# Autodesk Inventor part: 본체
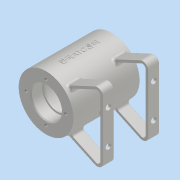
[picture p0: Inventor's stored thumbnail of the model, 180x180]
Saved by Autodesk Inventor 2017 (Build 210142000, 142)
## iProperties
Part Number: 본체
Material: 알루미늄 6061
Document SubType Name: Modeling
Designer: Administrator
Density: 2.7 g/cm^3
Appearance: 알루미늄 - 평지
Mass: 310.254 g
Surface Area: 354.969 cm^2
Volume: 114.909 cm^3
Author: Administrator
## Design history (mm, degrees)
sketch "스케치1"
  geometry: C1 r 29 at (0, 0); 1 further point
  constraints: 1 centre point, 1 coincident
  dimensions: "d0" = 58 diameter of C1
extrude "돌출1" new body sketch "스케치1" distance "d1" = 35; taper "d3" = 0 deg; dims "d2" = 35, "d4" = 0
sketch "스케치2"
  geometry: C1 r 21 at (0, 0); 1 further point
  constraints: 1 centre point, 1 coincident
  dimensions: "d5" = 42 diameter of C1
extrude "돌출2" cut sketch "스케치2" distance "d6" = 21; taper "d8" = 0 deg; dims "d7" = 21, "d9" = 0
sketch "스케치3"
  geometry: C1 r 14 at (0, 0); 1 further point
  constraints: 1 centre point, 1 coincident
  dimensions: "d10" = 28 diameter of C1
extrude "돌출3" cut sketch "스케치3" distance "d11" = 23; taper "d13" = 0 deg; dims "d12" = 23, "d14" = 0
sketch "스케치4"
  geometry: C1 r 14 at (0, 0) reference; C2 r 16 at (0, 0); 1 further point
  constraints: 1 centre point, 1 coincident
  dimensions: "d15" = 32 diameter of C2
extrude "돌출4" cut sketch "스케치4" distance "d16" = 12; taper "d17" = 0 deg
sketch "스케치5"
  geometry: C1 r 16 at (0, 0); 1 further point
  constraints: 1 centre point, 1 coincident
  dimensions: "d18" = 32 diameter of C1
extrude "돌출5" cut sketch "스케치5" distance "d19" = 12; taper "d20" = 0 deg
sketch "스케치6"
  geometry: 2 further points
  constraints: 1 horizontal alignment
  dimensions: "d21" = 21 distance of point (0, 0) point (-21, 0)
hole "구멍1" sketch "스케치6" at (-21, 0) diameter "d22" = 3.242; stored, may be unused: countersink angle "d26" = 90 deg, drill point angle "d28" = 118 deg; dims "d23" = 8, "d24" = 4, "d25" = 2, "d27" = 10
sketch "스케치7"
  geometry: 2 further points
  constraints: 1 horizontal alignment
  dimensions: "d32" = 21 distance of point (0, 0) point (-21, 0)
hole "구멍2" sketch "스케치7" at (-21, 0) diameter "d33" = 3.242; stored, may be unused: countersink angle "d37" = 90 deg, drill point angle "d39" = 118 deg; dims "d34" = 8, "d35" = 4, "d36" = 2, "d38" = 10
sketch "스케치8"
  geometry: L1 (0, 0)-(-30.07, -10.945); L2 (0, 0)-(32, 0); L3 (-30.07, -10.945)-(-28.018, -16.583); L4 (-23.397, -8.516)-(-21.345, -14.154); L5 (-21.345, -14.154)-(-28.018, -16.583)
  constraints: 10 end point, 2 perpendicular, 1 equal length, 1 horizontal, 1 parallel, 1 point on line
  dimensions: "d43" = 160 deg angle of L1 L2; "d45" = 32 distance of L1.start L1.end; "d46" = 6 distance of L1.end L3.end; "d47" = 6.67327 horizontal distance of L4.end L3.end
revolve "회전1" sketch "스케치8" stored, may be unused: angle "d48" = 90 deg
sketch "스케치9"
  geometry: 2 further points
  constraints: 2 coincident
hole "구멍3" sketch "스케치9" at (0, 0) diameter "d49" = 5.188; stored, may be unused: countersink angle "d53" = 90 deg, drill point angle "d55" = 118 deg; dims "d50" = 20, "d51" = 4, "d52" = 2, "d54" = 29
node "작업 평면1"
sketch "스케치12"
  geometry: C1 r 5 at (0, 0); 1 further point
  constraints: 1 centre point, 1 coincident
  dimensions: "d59" = 10 diameter of C1
extrude "돌출6" join sketch "스케치12" stored distance "d60" = 10; taper "d61" = 0 deg
node "작업 평면2"
sketch "스케치13"
  geometry: L1 (-55, 30.582)-(-55, -30.582); L2 (0, 0)-(0, -50.41); L3 (-46.464, -36.02)-(-17.993, -22.743); L4 (-55, -40)-(-23.585, -40); L5 (-46.464, 36.02)-(-17.993, 22.743); L6 (-55, 40)-(-23.585, 40); L7 (-20.438, 20.574)-(-47.732, 33.301); L8 (-52, 30.582)-(-52, -30.582); L9 (-47.732, -33.301)-(-20.438, -20.574); A1 r 29 centre (0, 0) between (-17.993, 22.743) and (-17.993, -22.743) reference; A2 r 6 centre (-49, -30.582) between (-55, -30.582) and (-46.464, -36.02); A3 r 6 centre (-49, 30.582) between (-46.464, 36.02) and (-55, 30.582); A4 r 3 centre (-49, 30.582) between (-47.732, 33.301) and (-52, 30.582); A5 r 3 centre (-49, -30.582) between (-52, -30.582) and (-47.732, -33.301); 2 further points
  constraints: 18 end point, 12 point on circle, 4 centre point, 4 point on line, 4 tangent, 2 equal length, 2 horizontal, 1 equal radius, 1 horizontal alignment, 1 midpoint, 1 parallel, 1 vertical, 2 other
  dimensions: "d63" = 55 distance from line of L1 point (0, 0); "d64" = 80 distance of L6.start L4.start; "d65" = 25 deg angle of L4 L3; "d66" = 25 deg angle of L5 L6; "d67" = 50.40972 distance of L2.start L2.end; "d71" = 6 radius of A2; "d72" = 3 distance between parallel lines of L5 L7; "d73" = 3 distance between parallel lines of L1 L8; "d74" = 3 distance between parallel lines of L3 L9
extrude "돌출7" join sketch "스케치13" distance "d75" = 12; taper "d76" = 0 deg
sketch "스케치14"
  geometry: L1 (0, 0)-(61.164, 0) reference; L2 (61.164, 0)-(61.164, 12) reference; L3 (0, 12)-(61.164, 12) reference; L4 (0, 0)-(0, 12) reference; C1 r 3 at (48.582, 6); C2 r 3 at (12.582, 6); 1 further point
  constraints: 2 centre point
  dimensions: "d77" = 6 diameter of C1; "d78" = 6 diameter of C2; "d80" = 6 distance from line of L3 C1.centre; "d81" = 6 distance from line of L3 C2.centre; "d82" = 36 distance of C2.centre C1.centre; "d83" = 18 horizontal distance of point (30.582, -18) C1.centre
extrude "돌출8" cut sketch "스케치14" distance "d84" = 12; taper "d85" = 0 deg
sketch "스케치15"
  geometry: 2 further points
  constraints: 1 coincident
hole "구멍4" sketch "스케치15" at (0, 0) diameter "d86" = 5.188; stored, may be unused: countersink angle "d90" = 90 deg, drill point angle "d92" = 118 deg; dims "d87" = 6, "d88" = 4, "d89" = 2, "d91" = 8
sketch "스케치16"
  geometry: C1 r 1.5 at (0, 0); 1 further point
  constraints: 1 centre point, 1 coincident
  dimensions: "d93" = 3 diameter of C1
extrude "돌출9" cut sketch "스케치16" distance "d94" = 34.75; taper "d95" = 0 deg
fillet "모깎기1" dims "d96" = 1
fillet "모깎기2" dims "d97" = 0.5
fillet "모깎기3" dims "d98" = 0.5
fillet "모깎기4" dims "d99" = 0.3
fillet "모깎기5" dims "d100" = 3
fillet "모깎기6" dims "d101" = 3
chamfer "모따기1" distance "d102" = 1; stored, may be unused: second distance "d103" = 2, angle "d104" = 45 deg
node "작업 평면4"
sketch "스케치18"
  geometry: L1 (-29, -35)-(29, -35) reference; L2 (-29, -35)-(-29, 35) reference; 2 further points
  constraints: 1 other
  dimensions: "d111" = 35 distance from line of L1 point (0, 0); "d112" = 29 distance from line of L2 point (0, 0)
feature "엠보싱2" sketch "스케치18" dims "d113" = 0.5, "d114" = 0
node "솔리드1"
pattern_circular "원형 패턴1" dims angle "d30" = 360 deg
pattern_circular "원형 패턴2" dims angle "d41" = 360 deg
mirror "미러1"
node "투영된 루프1"
other parameters: "d58" = -32, "d62" = 18, "d110" = 29
